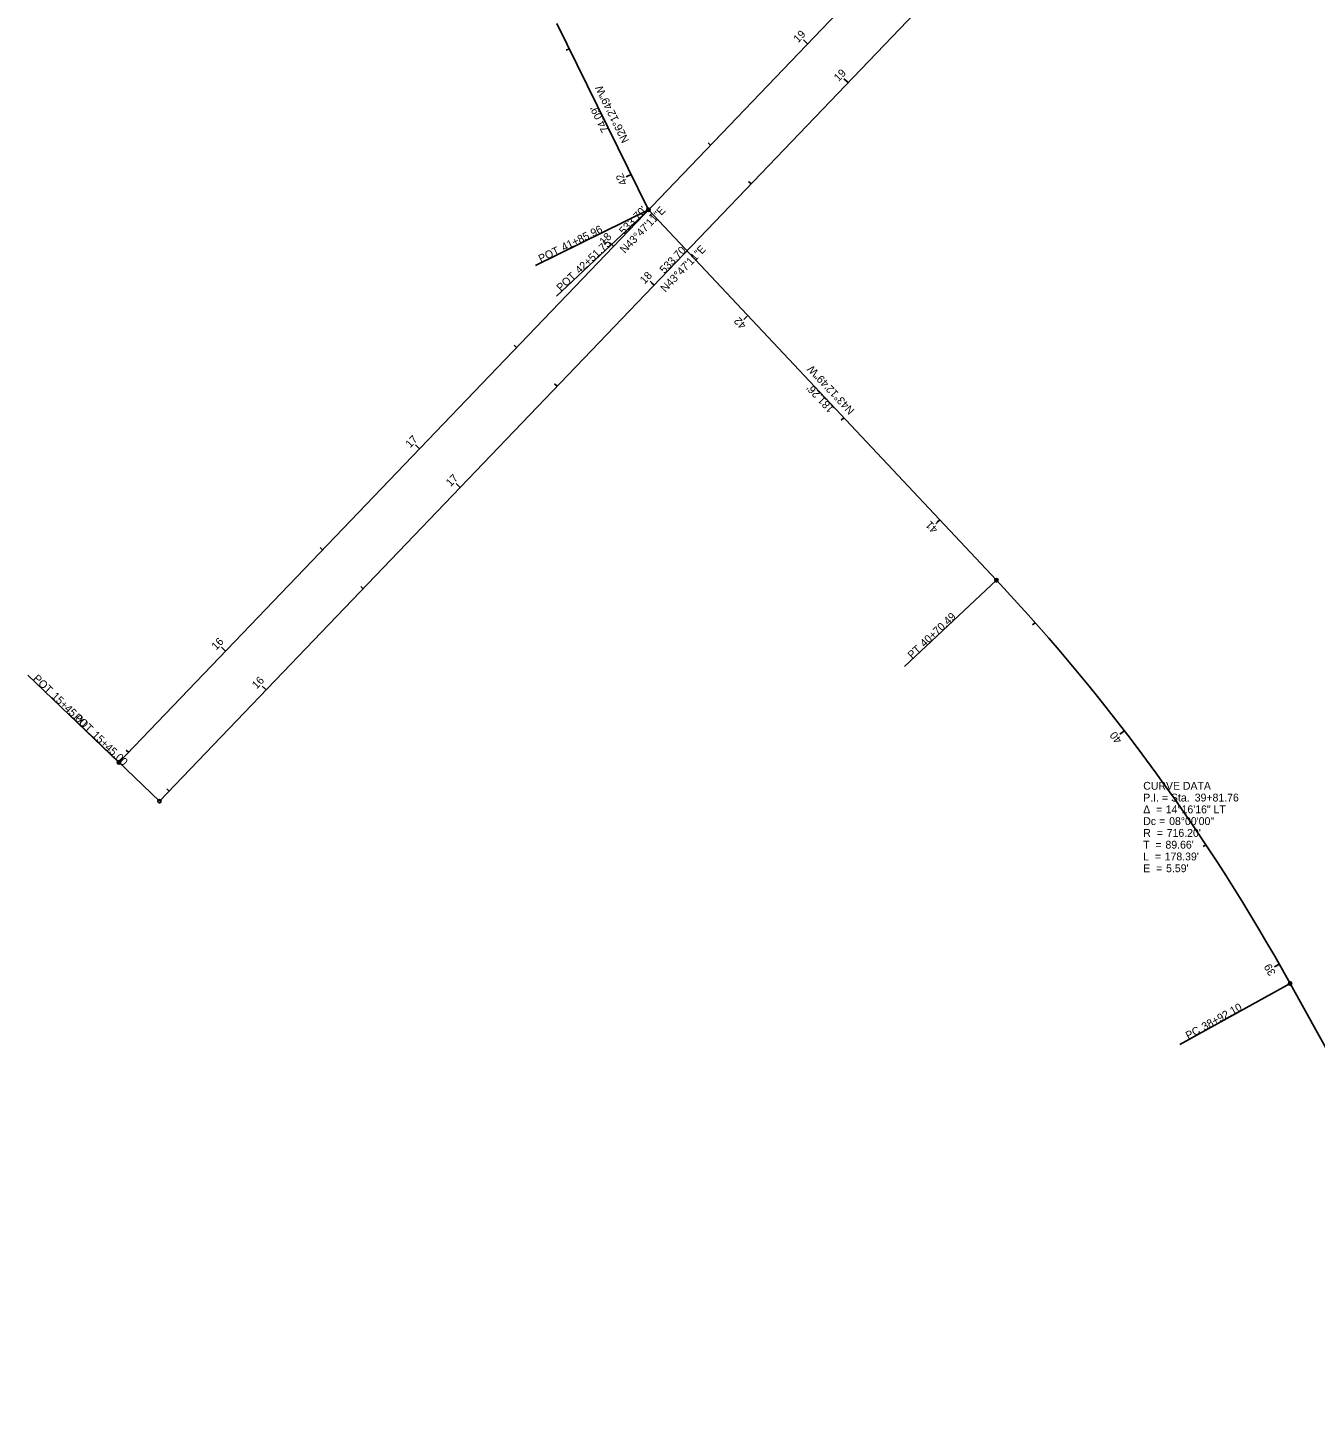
# Model space of a CAD drawing. Extents: x 1363001 to 1363920, y 487582 to 489802.
# Drawn here: x 1363047.6 to 1363506.8, y 488096.9 to 488594.8 of the extents above; entities that cross this region are included whole.
import ezdxf

# ---------------------------------------------------------------- set-up
doc = ezdxf.new("R2010")
doc.units = 0
for name, color, linetype in [('BR_X_SV_Beam_Seat', 7, 'Continuous'), ('BR_X_SV_Bottom_of_Beam_Text', 7, 'Continuous'), ('BR_X_SV_Deck_Top', 7, 'Continuous'), ('BR_X_SV_Deck_Top_Text', 7, 'Continuous'), ('BR_X_SV_Shot_Marker', 7, 'Continuous'), ('DR_X_Cells', 7, 'Continuous'), ('DR_X_Elev_Flow', 7, 'Continuous'), ('PV_X_COP', 7, 'Continuous'), ('PV_X_Curb', 7, 'Continuous'), ('PV_X_EOP', 7, 'Continuous'), ('PV_X_Shoulder_Aggregate', 7, 'Continuous'), ('RD_X_Cells', 7, 'Continuous'), ('RD_X_Concrete_Pad', 7, 'Continuous'), ('RD_X_GR_Lt', 7, 'Continuous'), ('RD_X_GR_Rt', 7, 'Continuous'), ('SG_X_Interconnect_Cable', 7, 'Continuous'), ('SG_X_PullBox', 7, 'Continuous'), ('SN_X_Public', 7, 'Continuous'), ('SV_P_Aerial_Targets', 7, 'Continuous'), ('SV_P_Control_Cells_Set', 7, 'Continuous'), ('SV_P_Mon_Cells_Set', 7, 'Continuous'), ('SV_X_Break_Lines', 7, 'Continuous'), ('SV_X_Mon_Cells_Found', 7, 'Continuous'), ('SV_X_Random_Point', 7, 'Continuous'), ('SV_X_Shot_Marker', 7, 'Continuous'), ('SV_X_Text_Comment', 7, 'Continuous'), ('SV_X_Text_Name', 7, 'Continuous'), ('UT_X_Electric', 7, 'Continuous'), ('UT_X_Electric_Cells', 7, 'Continuous'), ('UT_X_Water', 7, 'Continuous')]:
    doc.layers.add(name, color=color, linetype=linetype)

msp = doc.modelspace()

# ---------------------------------------------------------------- linework, layer by layer
at = {"layer": 'BR_X_SV_Bottom_of_Beam_Text'}
for p, q in [((1363269.04, 488529.91), (1363228.67, 488510.03)), ((1363269.04, 488529.91), (1363236.24, 488499.1)), ((1363393.15, 488397.81), (1363360.35, 488366.99)), ((1363080.13, 488332.82), (1363047.64, 488363.96)), ((1363497.93, 488254), (1363458.55, 488232.22))]:
    msp.add_line(p, q, dxfattribs=at)
for centre in [(1363269.04, 488529.91), (1363269.04, 488529.91), (1363393.15, 488397.81), (1363080.13, 488332.82), (1363497.93, 488254)]:
    msp.add_circle(centre, 0.6, dxfattribs=at)
at = {"layer": 'BR_X_SV_Deck_Top'}
for p, q in [((1363340.22, 488575.27), (1363338.77, 488576.65)), ((1363305.62, 488539.17), (1363304.75, 488540)), ((1363271.02, 488503.08), (1363269.58, 488504.46)), ((1363236.42, 488466.98), (1363235.56, 488467.81)), ((1363201.82, 488430.88), (1363200.38, 488432.27)), ((1363167.22, 488394.79), (1363166.36, 488395.62)), ((1363132.63, 488358.69), (1363131.18, 488360.08)), ((1363098.03, 488322.59), (1363097.16, 488323.43))]:
    msp.add_line(p, q, dxfattribs=at)
at = {"layer": 'BR_X_SV_Deck_Top_Text'}
msp.add_line((1363094.57, 488318.99), (1363463.87, 488704.28), dxfattribs=at)
at = {"layer": 'BR_X_SV_Shot_Marker'}
for p, q in [((1363325.78, 488589.11), (1363324.33, 488590.49)), ((1363240.75, 488587.36), (1363239.67, 488586.83)), ((1363291.18, 488553.01), (1363290.31, 488553.84)), ((1363262.84, 488542.51), (1363261.04, 488541.62)), ((1363270.24, 488528.63), (1363269.36, 488527.81)), ((1363256.58, 488516.92), (1363255.14, 488518.3)), ((1363304.47, 488492.19), (1363303.01, 488490.82)), ((1363221.98, 488480.82), (1363221.12, 488481.65)), ((1363338.71, 488455.75), (1363337.83, 488454.93)), ((1363187.38, 488444.72), (1363185.94, 488446.11)), ((1363372.94, 488419.31), (1363371.49, 488417.94)), ((1363152.79, 488408.63), (1363151.92, 488409.46)), ((1363406.96, 488382.67), (1363406.07, 488381.88)), ((1363118.19, 488372.53), (1363116.74, 488373.91)), ((1363438.81, 488344.14), (1363437.23, 488342.92)), ((1363083.59, 488336.43), (1363082.72, 488337.26)), ((1363467.89, 488303.48), (1363466.89, 488302.82)), ((1363494.07, 488260.89), (1363492.33, 488259.91))]:
    msp.add_line(p, q, dxfattribs=at)
at = {"layer": 'PV_X_COP'}
for p, q in [((1363340.22, 488575.27), (1363339.35, 488576.1)), ((1363271.02, 488503.08), (1363270.15, 488503.91)), ((1363201.82, 488430.88), (1363200.96, 488431.71)), ((1363132.63, 488358.69), (1363131.76, 488359.52))]:
    msp.add_line(p, q, dxfattribs=at)
at = {"layer": 'PV_X_Curb'}
for p, q in [((1363269.04, 488529.91), (1363228.67, 488510.03)), ((1363269.04, 488529.91), (1363236.24, 488499.1)), ((1363393.15, 488397.81), (1363360.35, 488366.99)), ((1363080.13, 488332.82), (1363047.64, 488363.96)), ((1363497.93, 488254), (1363458.55, 488232.22))]:
    msp.add_line(p, q, dxfattribs=at)
for centre in [(1363269.04, 488529.91), (1363269.04, 488529.91), (1363393.15, 488397.81), (1363080.13, 488332.82), (1363497.93, 488254)]:
    msp.add_circle(centre, 0.6, dxfattribs=at)
at = {"layer": 'PV_X_Shoulder_Aggregate'}
msp.add_line((1363094.57, 488318.99), (1363062.08, 488350.12), dxfattribs=at)
msp.add_circle((1363094.57, 488318.99), 0.6, dxfattribs=at)
at = {"layer": 'RD_X_Concrete_Pad'}
msp.add_line((1363094.57, 488318.99), (1363062.08, 488350.12), dxfattribs=at)
msp.add_circle((1363094.57, 488318.99), 0.6, dxfattribs=at)
at = {"layer": 'RD_X_GR_Rt'}
msp.add_line((1363438.81, 488344.14), (1363437.23, 488342.92), dxfattribs=at)
at = {"layer": 'SG_X_PullBox'}
for p, q in [((1363325.78, 488589.11), (1363324.91, 488589.94)), ((1363262.84, 488542.51), (1363261.76, 488541.98)), ((1363256.58, 488516.92), (1363255.72, 488517.75)), ((1363304.47, 488492.19), (1363303.6, 488491.37)), ((1363187.38, 488444.72), (1363186.52, 488445.55)), ((1363372.94, 488419.31), (1363372.07, 488418.49)), ((1363118.19, 488372.53), (1363117.32, 488373.36)), ((1363438.81, 488344.14), (1363437.23, 488342.92)), ((1363494.07, 488260.89), (1363493.02, 488260.3))]:
    msp.add_line(p, q, dxfattribs=at)
at = {"layer": 'SN_X_Public'}
msp.add_line((1363094.57, 488318.99), (1363062.08, 488350.12), dxfattribs=at)
msp.add_circle((1363094.57, 488318.99), 0.6, dxfattribs=at)
at = {"layer": 'SV_X_Shot_Marker'}
for p, q in [((1363393.15, 488397.81), (1363269.04, 488529.91)), ((1363497.93, 488254), (1363760.27, 487779.61))]:
    msp.add_line(p, q, dxfattribs=at)
msp.add_arc((1362871.18, 487907.41), 716.2, 28.94245, 43.21359, dxfattribs=at)
at = {"layer": 'SV_X_Text_Comment'}
for p, q in [((1363080.13, 488332.82), (1363449.43, 488718.12)), ((1363269.04, 488529.91), (1363236.31, 488596.38)), ((1363393.15, 488397.81), (1363269.04, 488529.91)), ((1363760.27, 487779.61), (1363497.93, 488254))]:
    msp.add_line(p, q, dxfattribs=at)
msp.add_arc((1362871.18, 487907.41), 716.2, 28.94245, 43.21359, dxfattribs=at)
at = {"layer": 'SV_X_Text_Name'}
for p, q in [((1363268.37, 488529.24), (1363269.7, 488530.58)), ((1363268.37, 488530.58), (1363269.7, 488529.24)), ((1363392.48, 488397.14), (1363393.82, 488398.47)), ((1363392.48, 488398.47), (1363393.82, 488397.14)), ((1363079.46, 488332.16), (1363080.8, 488333.49)), ((1363079.46, 488333.49), (1363080.8, 488332.16))]:
    msp.add_line(p, q, dxfattribs=at)
at = {"layer": 'UT_X_Water'}
for p, q in [((1363269.04, 488529.91), (1363228.67, 488510.03)), ((1363269.04, 488529.91), (1363236.24, 488499.1)), ((1363393.15, 488397.81), (1363360.35, 488366.99)), ((1363080.13, 488332.82), (1363047.64, 488363.96)), ((1363497.93, 488254), (1363458.55, 488232.22))]:
    msp.add_line(p, q, dxfattribs=at)
for centre in [(1363269.04, 488529.91), (1363269.04, 488529.91), (1363393.15, 488397.81), (1363080.13, 488332.82), (1363497.93, 488254)]:
    msp.add_circle(centre, 0.6, dxfattribs=at)

# ---------------------------------------------------------------- texts
at = {"layer": 'BR_X_SV_Beam_Seat'}
for s, rotation, p in [('N26°12\'49"W', 116.2136, (1363262.22, 488554.62)), ('N43°47\'11"E', 46.2136, (1363260.61, 488514.18)), ('N43°12\'49"W', 133.2136, (1363342.72, 488458.5))]:
    msp.add_text(s, height=2.8, rotation=rotation, dxfattribs=at).set_placement(p)
at = {"layer": 'BR_X_SV_Bottom_of_Beam_Text'}
for s, rotation, p in [('41+85.96', 26.2136, (1363238.81, 488515.08)), ('POT', 26.2136, (1363230.62, 488511.05)), ('42+51.75', 43.2136, (1363244.46, 488506.89)), ('POT', 43.2136, (1363237.81, 488500.63)), ('40+70.49', 43.2136, (1363367.5, 488373.77)), ('PT', 43.2136, (1363363.06, 488369.6)), ('POT', 316.2136, (1363049.27, 488362.47)), ('15+45.00', 316.2136, (1363055.86, 488356.15)), ('38+92.10', 28.9424, (1363467.31, 488237.12)), ('PC', 28.9424, (1363461.6, 488233.97))]:
    msp.add_text(s, height=2.8, rotation=rotation, dxfattribs=at).set_placement(p)
at = {"layer": 'BR_X_SV_Deck_Top'}
for s, p in [('19', (1363336.88, 488575.47)), ('18', (1363267.67, 488503.26)), ('17', (1363198.46, 488430.99)), ('16', (1363129.27, 488358.87))]:
    msp.add_text(s, height=2.8, rotation=46.2136, dxfattribs=at).set_placement(p)
at = {"layer": 'BR_X_SV_Shot_Marker'}
for s, rotation, p in [('19', 46.2136, (1363322.44, 488589.31)), ('42', 116.2136, (1363261.56, 488539.44)), ('18', 46.2136, (1363253.23, 488517.1)), ('42', 133.2136, (1363304.15, 488488.89)), ('17', 46.2136, (1363184.02, 488444.83)), ('41', 133.2136, (1363372.51, 488416.13)), ('16', 46.2136, (1363114.83, 488372.71)), ('40', 127.5744, (1363438.13, 488340.85)), ('39', 119.5744, (1363492.92, 488257.75))]:
    msp.add_text(s, height=2.8, rotation=rotation, dxfattribs=at).set_placement(p)
at = {"layer": 'DR_X_Cells'}
for s, rotation, p in [("74.09'", 116.2136, (1363255.02, 488558.28)), ("533.70'", 46.2136, (1363260.26, 488520.82)), ("181.26'", 133.2136, (1363335.5, 488459.1))]:
    msp.add_text(s, height=2.8, rotation=rotation, dxfattribs=at).set_placement(p)
at = {"layer": 'DR_X_Elev_Flow'}
for s, p in [('CURVE DATA', (1363445.54, 488323.1)), ('P.I. = Sta. ', (1363445.54, 488318.9)), ('39+81.76', (1363463.91, 488318.9)), ('Δ  = ', (1363445.54, 488314.7)), ('14°16\'16" LT', (1363453.56, 488314.7)), ('Dc = ', (1363445.54, 488310.5)), ('08°00\'00"', (1363454.78, 488310.5)), ('R  = ', (1363445.54, 488306.3)), ("716.20'", (1363453.91, 488306.3)), ('T  = ', (1363445.54, 488302.1)), ("89.66'", (1363453.47, 488302.1)), ('L  = ', (1363445.54, 488297.9)), ("178.39'", (1363453.19, 488297.9)), ('E  = ', (1363445.54, 488293.7)), ("5.59'", (1363453.69, 488293.7))]:
    msp.add_text(s, height=2.8, dxfattribs=at).set_placement(p)
at = {"layer": 'PV_X_Curb'}
for s, rotation, p in [('41+85.96', 26.2136, (1363238.81, 488515.08)), ('POT', 26.2136, (1363230.62, 488511.05)), ('42+51.75', 43.2136, (1363244.46, 488506.89)), ('POT', 43.2136, (1363237.81, 488500.63)), ('40+70.49', 43.2136, (1363367.5, 488373.77)), ('PT', 43.2136, (1363363.06, 488369.6)), ('POT', 316.2136, (1363049.27, 488362.47)), ('15+45.00', 316.2136, (1363055.86, 488356.15)), ('38+92.10', 28.9424, (1363467.31, 488237.12)), ('PC', 28.9424, (1363461.6, 488233.97))]:
    msp.add_text(s, height=2.8, rotation=rotation, dxfattribs=at).set_placement(p)
at = {"layer": 'PV_X_EOP'}
msp.add_text('N43°47\'11"E', height=2.8, rotation=46.2136, dxfattribs=at).set_placement((1363275.05, 488500.34))
at = {"layer": 'PV_X_Shoulder_Aggregate'}
for s, p in [('POT', (1363063.71, 488348.63)), ('15+45.00', (1363070.3, 488342.31))]:
    msp.add_text(s, height=2.8, rotation=316.2136, dxfattribs=at).set_placement(p)
at = {"layer": 'RD_X_Cells'}
msp.add_text('N43°47\'11"E', height=2.8, rotation=46.2136, dxfattribs=at).set_placement((1363275.05, 488500.34))
at = {"layer": 'RD_X_Concrete_Pad'}
for s, p in [('POT', (1363063.71, 488348.63)), ('15+45.00', (1363070.3, 488342.31))]:
    msp.add_text(s, height=2.8, rotation=316.2136, dxfattribs=at).set_placement(p)
at = {"layer": 'RD_X_GR_Lt'}
for s, rotation, p in [("74.09'", 116.2136, (1363255.02, 488558.28)), ("533.70'", 46.2136, (1363260.26, 488520.82)), ("181.26'", 133.2136, (1363335.5, 488459.1))]:
    msp.add_text(s, height=2.8, rotation=rotation, dxfattribs=at).set_placement(p)
at = {"layer": 'RD_X_GR_Rt'}
msp.add_text('40', height=2.8, rotation=127.5744, dxfattribs=at).set_placement((1363438.13, 488340.85))
at = {"layer": 'SG_X_Interconnect_Cable'}
for s, rotation, p in [('N26°12\'49"W', 116.2136, (1363262.22, 488554.62)), ('N43°47\'11"E', 46.2136, (1363260.61, 488514.18)), ('N43°12\'49"W', 133.2136, (1363342.72, 488458.5))]:
    msp.add_text(s, height=2.8, rotation=rotation, dxfattribs=at).set_placement(p)
at = {"layer": 'SG_X_PullBox'}
msp.add_text('40', height=2.8, rotation=127.5744, dxfattribs=at).set_placement((1363438.13, 488340.85))
at = {"layer": 'SN_X_Public'}
for s, p in [('POT', (1363063.71, 488348.63)), ('15+45.00', (1363070.3, 488342.31))]:
    msp.add_text(s, height=2.8, rotation=316.2136, dxfattribs=at).set_placement(p)
at = {"layer": 'SV_P_Aerial_Targets'}
msp.add_text("533.70'", height=2.8, rotation=46.2136, dxfattribs=at).set_placement((1363274.7, 488506.98))
at = {"layer": 'SV_P_Control_Cells_Set'}
for s, p in [('CURVE DATA', (1363445.54, 488323.1)), ('P.I. = Sta. ', (1363445.54, 488318.9)), ('39+81.76', (1363463.91, 488318.9)), ('Δ  = ', (1363445.54, 488314.7)), ('14°16\'16" LT', (1363453.56, 488314.7)), ('Dc = ', (1363445.54, 488310.5)), ('08°00\'00"', (1363454.78, 488310.5)), ('R  = ', (1363445.54, 488306.3)), ("716.20'", (1363453.91, 488306.3)), ('T  = ', (1363445.54, 488302.1)), ("89.66'", (1363453.47, 488302.1)), ('L  = ', (1363445.54, 488297.9)), ("178.39'", (1363453.19, 488297.9)), ('E  = ', (1363445.54, 488293.7)), ("5.59'", (1363453.69, 488293.7))]:
    msp.add_text(s, height=2.8, dxfattribs=at).set_placement(p)
at = {"layer": 'SV_P_Mon_Cells_Set'}
msp.add_text('N43°47\'11"E', height=2.8, rotation=46.2136, dxfattribs=at).set_placement((1363275.05, 488500.34))
at = {"layer": 'SV_X_Break_Lines'}
for s, rotation, p in [("74.09'", 116.2136, (1363255.02, 488558.28)), ("533.70'", 46.2136, (1363260.26, 488520.82)), ("181.26'", 133.2136, (1363335.5, 488459.1))]:
    msp.add_text(s, height=2.8, rotation=rotation, dxfattribs=at).set_placement(p)
at = {"layer": 'SV_X_Mon_Cells_Found'}
msp.add_text("533.70'", height=2.8, rotation=46.2136, dxfattribs=at).set_placement((1363274.7, 488506.98))
at = {"layer": 'SV_X_Random_Point'}
msp.add_text("533.70'", height=2.8, rotation=46.2136, dxfattribs=at).set_placement((1363274.7, 488506.98))
at = {"layer": 'UT_X_Electric'}
for s, p in [('CURVE DATA', (1363445.54, 488323.1)), ('P.I. = Sta. ', (1363445.54, 488318.9)), ('39+81.76', (1363463.91, 488318.9)), ('Δ  = ', (1363445.54, 488314.7)), ('14°16\'16" LT', (1363453.56, 488314.7)), ('Dc = ', (1363445.54, 488310.5)), ('08°00\'00"', (1363454.78, 488310.5)), ('R  = ', (1363445.54, 488306.3)), ("716.20'", (1363453.91, 488306.3)), ('T  = ', (1363445.54, 488302.1)), ("89.66'", (1363453.47, 488302.1)), ('L  = ', (1363445.54, 488297.9)), ("178.39'", (1363453.19, 488297.9)), ('E  = ', (1363445.54, 488293.7)), ("5.59'", (1363453.69, 488293.7))]:
    msp.add_text(s, height=2.8, dxfattribs=at).set_placement(p)
at = {"layer": 'UT_X_Electric_Cells'}
for s, rotation, p in [('N26°12\'49"W', 116.2136, (1363262.22, 488554.62)), ('N43°47\'11"E', 46.2136, (1363260.61, 488514.18)), ('N43°12\'49"W', 133.2136, (1363342.72, 488458.5))]:
    msp.add_text(s, height=2.8, rotation=rotation, dxfattribs=at).set_placement(p)
at = {"layer": 'UT_X_Water'}
for s, rotation, p in [('41+85.96', 26.2136, (1363238.81, 488515.08)), ('POT', 26.2136, (1363230.62, 488511.05)), ('42+51.75', 43.2136, (1363244.46, 488506.89)), ('POT', 43.2136, (1363237.81, 488500.63)), ('40+70.49', 43.2136, (1363367.5, 488373.77)), ('PT', 43.2136, (1363363.06, 488369.6)), ('POT', 316.2136, (1363049.27, 488362.47)), ('15+45.00', 316.2136, (1363055.86, 488356.15)), ('38+92.10', 28.9424, (1363467.31, 488237.12)), ('PC', 28.9424, (1363461.6, 488233.97))]:
    msp.add_text(s, height=2.8, rotation=rotation, dxfattribs=at).set_placement(p)

doc.saveas('drawing.dxf')
